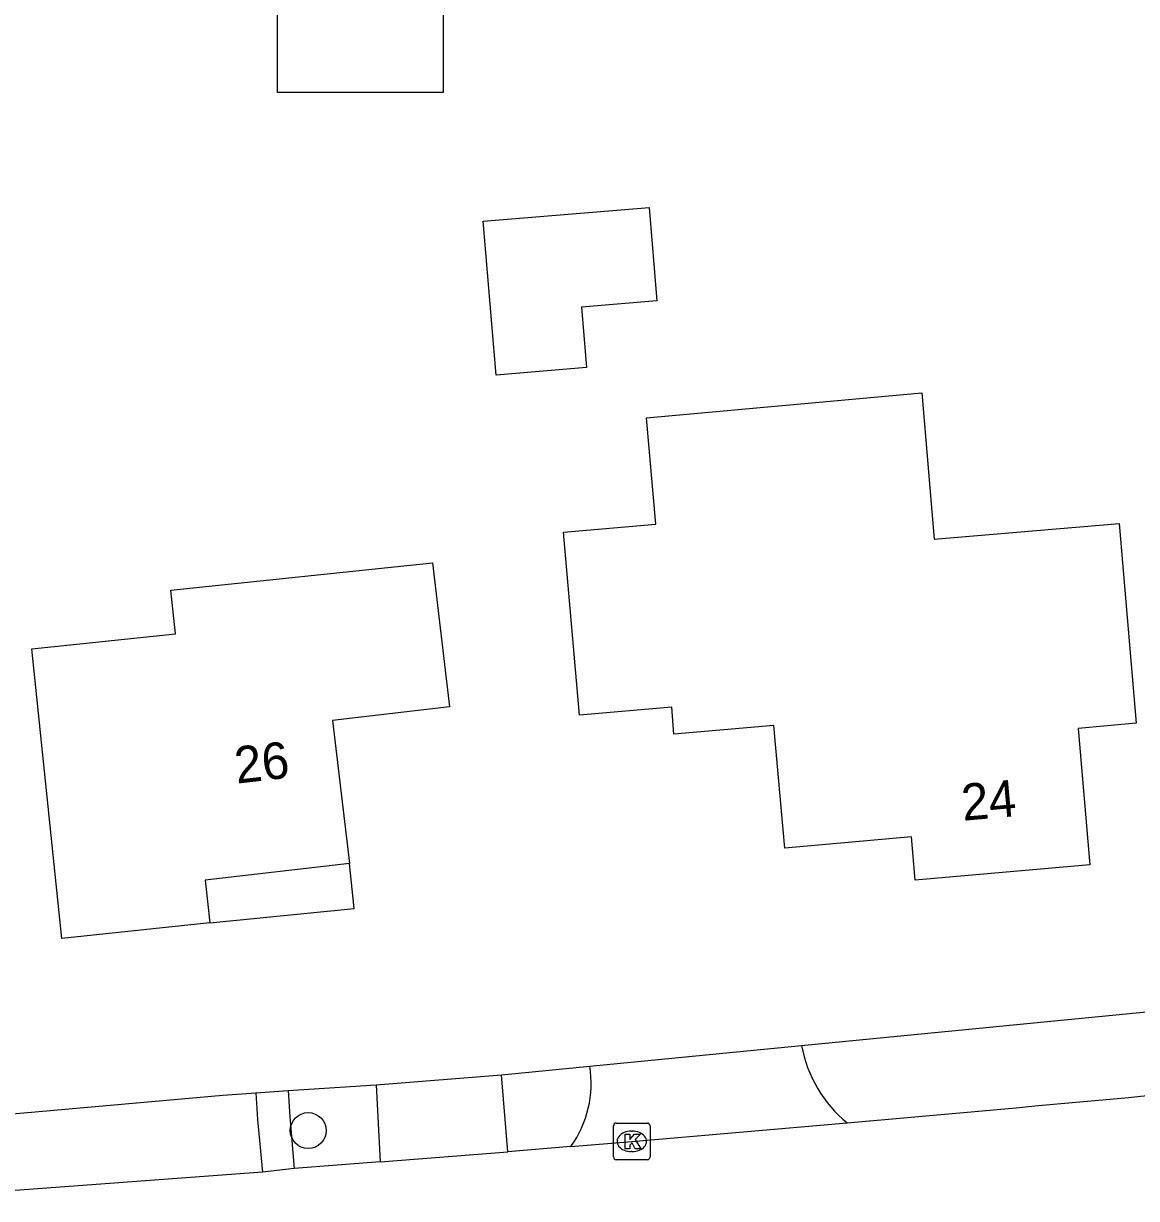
# Model space of a CAD drawing. Extents: x 162675 to 163482, y 379761 to 381227.
# Drawn here: x 163114.71 to 163145.1, y 380777.62 to 380809.71 of the extents above; entities that cross this region are included whole.
import ezdxf

# ---------------------------------------------------------------- set-up
doc = ezdxf.new("R2010")
doc.units = 0
for name, color, linetype in [('IMGEO_Berm_groen', 7, 'Continuous'), ('IMGEO_Boom', 7, 'Continuous'), ('IMGEO_Groenvoorziening', 7, 'Continuous'), ('IMGEO_Kolk', 7, 'Continuous'), ('IMGEO_Pand', 7, 'Continuous'), ('IMGEO_Pand_nummerreeks', 7, 'Continuous'), ('IMGEO_Pand_overbouw', 7, 'Continuous'), ('IMGEO_Rijbaan_lokaal_gesloten', 7, 'Continuous'), ('IMGEO_Rijbaan_lokaal_halfverhard', 7, 'Continuous'), ('IMGEO_Rijbaan_lokaal_open', 7, 'Continuous'), ('IMGEO_Voetpad_open', 7, 'Continuous')]:
    doc.layers.add(name, color=color, linetype=linetype)

msp = doc.modelspace()

# ---------------------------------------------------------------- linework, layer by layer
at = {"layer": 'IMGEO_Berm_groen'}
msp.add_lwpolyline([(163135.951, 380781.798), (163169.717, 380785.094)], dxfattribs=at)
at = {"layer": 'IMGEO_Boom'}
msp.add_circle((163122.48, 380779.476), 0.489, dxfattribs=at)
at = {"layer": 'IMGEO_Groenvoorziening'}
for points in [[(163106.322, 380830.801), (163103.397, 380830.811), (163103.788, 380827.01), (163107.334, 380784.216), (163107.736, 380779.339), (163120.148, 380780.444), (163121.048, 380780.505)], [(163127.759, 380780.998), (163130.169, 380781.233)], [(163121.933, 380780.565), (163124.339, 380780.727)]]:
    msp.add_lwpolyline(points, dxfattribs=at)
at = {"layer": 'IMGEO_Kolk'}
for p, q in [((163130.815, 380778.754), (163130.815, 380779.606)), ((163130.89, 380779.68), (163131.742, 380779.68)), ((163131.816, 380779.606), (163131.816, 380778.754)), ((163131.303, 380779.46), (163131.328, 380779.46)), ((163131.326, 380778.9), (163131.301, 380778.9)), ((163131.742, 380778.68), (163130.89, 380778.68))]:
    msp.add_line(p, q, dxfattribs=at)
for points in [[(163130.815, 380778.754), (163130.815, 380779.606)], [(163130.89, 380779.68), (163131.742, 380779.68)], [(163131.816, 380779.606), (163131.816, 380778.754)], [(163131.136, 380779.38), (163131.259, 380779.38), (163131.259, 380779.229), (163131.389, 380779.38), (163131.553, 380779.38), (163131.407, 380779.229), (163131.56, 380778.98), (163131.408, 380778.98), (163131.323, 380779.144), (163131.259, 380779.077), (163131.259, 380778.98), (163131.136, 380778.98), (163131.136, 380779.38)], [(163131.742, 380778.68), (163130.89, 380778.68)]]:
    msp.add_lwpolyline(points, dxfattribs=at)
for centre, start, end in [((163130.892, 380779.604), 91.552, 178.448), ((163130.892, 380779.604), 91.552, 178.448), ((163131.74, 380779.604), 1.552, 88.448), ((163131.74, 380779.604), 1.552, 88.448), ((163130.892, 380778.756), 181.552, 268.448), ((163130.892, 380778.756), 181.552, 268.448), ((163131.74, 380778.756), 271.552, 358.448), ((163131.74, 380778.756), 271.552, 358.448)]:
    msp.add_arc(centre, 0.0765, start, end, dxfattribs=at)
for centre, major_axis, ratio, start_param, end_param in [((163131.302, 380779.18), (-0.387, 0.002), 0.722429, 4.712389, 7.853982), ((163131.327, 380779.18), (-0.39, 0.002), 0.717154, 1.570796, 4.712389)]:
    msp.add_ellipse(centre, major_axis=major_axis, ratio=ratio, start_param=start_param, end_param=end_param, dxfattribs=at)
at = {"layer": 'IMGEO_Pand'}
for points in [[(163126.163, 380807.83), (163121.645, 380807.83), (163121.645, 380811.548), (163126.163, 380811.548), (163126.163, 380807.83)], [(163127.262, 380804.312), (163131.789, 380804.687), (163132, 380802.136), (163129.943, 380801.965), (163130.08, 380800.311), (163127.61, 380800.107), (163127.262, 380804.312)], [(163144.626, 380796.055), (163145.084, 380790.6), (163143.508, 380790.459), (163143.825, 380786.737), (163139.054, 380786.313), (163138.949, 380787.494), (163135.492, 380787.187), (163135.199, 380790.538), (163132.467, 380790.303), (163132.409, 380791.035), (163129.885, 380790.818), (163129.449, 380795.82), (163131.975, 380796.041), (163131.722, 380798.943), (163139.239, 380799.621), (163139.574, 380795.631), (163144.626, 380796.055)], [(163123.606, 380786.766), (163119.671, 380786.312), (163119.794, 380785.145), (163115.754, 380784.718), (163114.935, 380792.636), (163118.855, 380793.037), (163118.726, 380794.231), (163125.875, 380794.976), (163126.336, 380791.047), (163123.147, 380790.672), (163123.606, 380786.766)]]:
    msp.add_lwpolyline(points, dxfattribs=at)
at = {"layer": 'IMGEO_Pand_overbouw'}
msp.add_lwpolyline([(163119.794, 380785.145), (163123.739, 380785.543), (163123.606, 380786.766), (163119.671, 380786.312)], close=True, dxfattribs=at)
at = {"layer": 'IMGEO_Rijbaan_lokaal_gesloten'}
for points in [[(163129.656, 380779.042), (163131.316, 380779.18), (163137.197, 380779.687)], [(163124.447, 380778.625), (163127.927, 380778.898)], [(163129.656, 380779.042), (163127.927, 380778.898)], [(163124.447, 380778.625), (163122.096, 380778.441)], [(163121.228, 380778.336), (163113.611, 380777.772), (163111.385, 380777.62)], [(163122.096, 380778.441), (163121.228, 380778.336)]]:
    msp.add_lwpolyline(points, dxfattribs=at)
msp.add_arc((162944.766, 382949.195), 2178.026, 275.068746, 275.934695, dxfattribs=at)
at = {"layer": 'IMGEO_Rijbaan_lokaal_halfverhard'}
msp.add_lwpolyline([(163130.169, 380781.233), (163135.951, 380781.798)], dxfattribs=at)
for centre, radius, start, end in [((163139.44, 380782.434), 3.546, 190.3309, 230.7708), ((163127.231, 380780.765), 2.975, 324.6016, 9.0427)]:
    msp.add_arc(centre, radius, start, end, dxfattribs=at)
at = {"layer": 'IMGEO_Rijbaan_lokaal_open'}
for points in [[(163124.339, 380780.727), (163127.759, 380780.998)], [(163127.927, 380778.898), (163127.759, 380780.998)], [(163124.339, 380780.727), (163124.447, 380778.625)]]:
    msp.add_lwpolyline(points, dxfattribs=at)
at = {"layer": 'IMGEO_Voetpad_open'}
for points in [[(163121.048, 380780.505), (163121.933, 380780.565)], [(163121.048, 380780.505), (163121.097, 380779.782), (163121.228, 380778.336)], [(163121.933, 380780.565), (163121.982, 380779.846), (163122.096, 380778.441)]]:
    msp.add_lwpolyline(points, dxfattribs=at)

# ---------------------------------------------------------------- texts
at = {"layer": 'IMGEO_Pand_nummerreeks'}
for s, rotation, p in [('26', 6.5814, (163120.528, 380788.948)), ('24', 5.0764, (163140.362, 380787.935))]:
    msp.add_text(s, height=1, rotation=rotation, dxfattribs=at).set_placement(p)

doc.saveas('drawing.dxf')
